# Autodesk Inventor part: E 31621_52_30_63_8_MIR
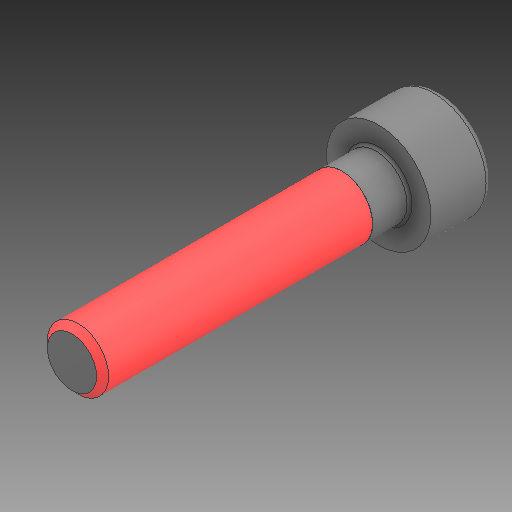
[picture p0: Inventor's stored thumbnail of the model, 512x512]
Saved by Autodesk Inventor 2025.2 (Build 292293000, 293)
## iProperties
Created: 2025-03
Part Number: E 31621_52_30_63_8_MIR
Material: Všeobecné
Document SubType Name: Modeling
Designer: Patrik
Stock Number: E 31621_52_30_63
Mass: 0.73741 g
Surface Area: 6.62537 cm^2
Volume: 0.73741 cm^3
Density: 1 g/cm^3
Appearance: Výchozí
Author: Patrik
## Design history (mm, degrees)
derived "E 31621_52_30_63_8.ipt"
feature "Těleso1::E 31621_52_30_63_8.ipt" dims "d0" = 10
tag "Prvek štítků1"
node "Těleso1"
